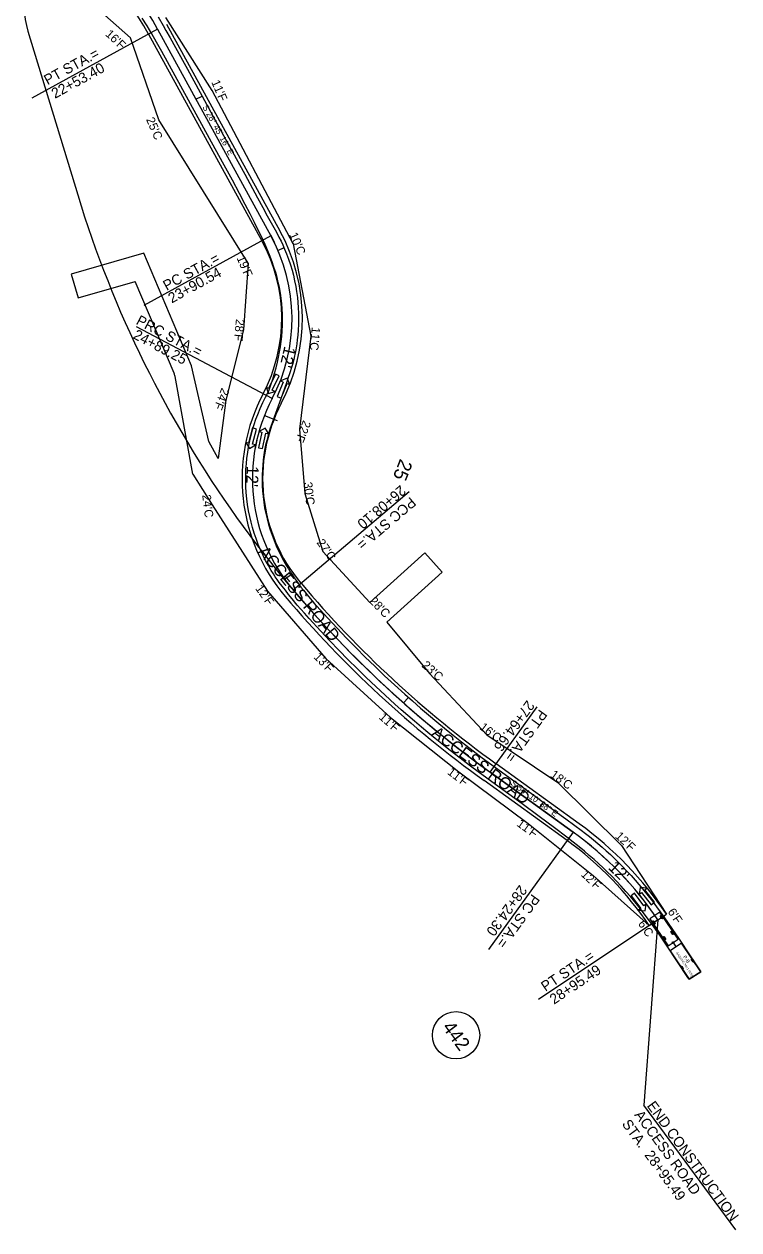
# Model space of a CAD drawing. Extents: x 1968740 to 1970715, y 796044 to 797557.
# Drawn here: x 1970299 to 1970715, y 796044 to 796745 of the extents above; entities that cross this region are included whole.
import ezdxf

# ---------------------------------------------------------------- set-up
doc = ezdxf.new("R2010")
doc.units = 0
for name, color, linetype in [('RD_EX_DV_TX_Prop', 7, 'Continuous'), ('RD_HC_CL_Rel', 7, 'Continuous'), ('RD_HC_Data_Rel', 7, 'Continuous'), ('RD_PD_ALT3_CL', 7, 'Continuous'), ('RD_PD_ALT4_CL', 7, 'Continuous'), ('RD_PD_ALT5_CL', 7, 'Continuous'), ('RD_PD_CstnLmt', 7, 'Continuous'), ('RD_PD_CstnLmt_TX', 7, 'Continuous'), ('RD_PD_Final_TrvlWay', 7, 'Continuous'), ('RD_PD_Final_TX', 7, 'Continuous'), ('RD_SHT_TX', 7, 'Continuous')]:
    doc.layers.add(name, color=color, linetype=linetype)

msp = doc.modelspace()

# ---------------------------------------------------------------- linework, layer by layer
at = {"layer": 'RD_EX_DV_TX_Prop'}
msp.add_circle((1970550.17, 796157.12), 13.75, dxfattribs=at)
at = {"layer": 'RD_HC_CL_Rel'}
for p, q in [((1970376.43, 796742.41), (1970442.41, 796622.18)), ((1970570.04, 796310.08), (1970618.4, 796275.17))]:
    msp.add_line(p, q, dxfattribs=at)
for centre, radius, start, end in [((1970201.1, 796646.2), 200, 28.75441, 54.46356), ((1970354.74, 796574.07), 100, 332.19932, 28.75441), ((1970531.65, 796480.79), 100, 152.19932, 220.29502), ((1970948.23, 796834.02), 646.17, 220.29502, 234.17718), ((1970501.34, 796113.01), 200, 33.78213, 54.17718)]:
    msp.add_arc(centre, radius, start, end, dxfattribs=at)
at = {"layer": 'RD_HC_Data_Rel'}
for p, q in [((1970376.43, 796742.41), (1970303.26, 796702.26)), ((1970396.45, 796705.94), (1970398.85, 796701.56)), ((1970398.85, 796701.56), (1970402.36, 796703.48)), ((1970442.41, 796622.18), (1970368.5, 796581.63)), ((1970442.15, 796622.66), (1970444.46, 796618.23)), ((1970446.56, 796613.69), (1970450.23, 796615.27)), ((1970443.2, 796527.43), (1970364.16, 796569.11)), ((1970438.7, 796517.67), (1970446.14, 796514.72)), ((1970434.23, 796503.37), (1970433.23, 796498.47)), ((1970431.69, 796483.57), (1970431.68, 796478.57)), ((1970455.38, 796416.12), (1970522.96, 796473.43)), ((1970450.4, 796422.51), (1970453.65, 796424.84)), ((1970519.59, 796350.48), (1970522.24, 796353.48)), ((1970570.04, 796310.08), (1970597.47, 796348.08)), ((1970598.69, 796289.4), (1970601.04, 796292.64)), ((1970618.4, 796275.17), (1970569.12, 796206.9)), ((1970667.57, 796224.22), (1970598.22, 796177.82))]:
    msp.add_line(p, q, dxfattribs=at)
at = {"layer": 'RD_PD_ALT3_CL'}
for p, q in [((1970376.43, 796742.41), (1970442.41, 796622.18)), ((1970618.4, 796275.17), (1970570.04, 796310.08))]:
    msp.add_line(p, q, dxfattribs=at)
for centre, radius, start, end in [((1970201.1, 796646.2), 200, 28.75441, 54.46356), ((1970354.74, 796574.07), 100, 332.19932, 28.75441), ((1970531.65, 796480.79), 100, 152.19932, 220.29502), ((1970948.23, 796834.02), 646.17, 220.29502, 234.17718), ((1970501.34, 796113.01), 200, 33.8013, 54.17718)]:
    msp.add_arc(centre, radius, start, end, dxfattribs=at)
at = {"layer": 'RD_PD_ALT4_CL'}
msp.add_line((1970301.07, 796741.13), (1970330.05, 796645.9), dxfattribs=at)
for centre, radius, start, end in [((1970350.34, 796756.12), 51.5, 165.49821, 196.92504), ((1970948.23, 796834.02), 646.17, 196.92504, 234.17718)]:
    msp.add_arc(centre, radius, start, end, dxfattribs=at)
at = {"layer": 'RD_PD_ALT5_CL'}
for p, q in [((1970376.43, 796742.41), (1970442.41, 796622.18)), ((1970618.4, 796275.17), (1970570.04, 796310.08)), ((1970668.78, 796228.71), (1970662.96, 796224.82)), ((1970662.96, 796224.82), (1970673.53, 796209.03)), ((1970662.96, 796224.82), (1970662.96, 796224.82)), ((1970679.35, 796212.92), (1970668.78, 796228.71)), ((1970669.13, 796226.59), (1970670.28, 796224.86)), ((1970669.23, 796226.66), (1970670.39, 796224.93)), ((1970669.34, 796226.73), (1970670.5, 796225)), ((1970664.57, 796223.54), (1970665.73, 796221.81)), ((1970664.68, 796223.61), (1970665.84, 796221.88)), ((1970664.79, 796223.69), (1970665.95, 796221.95)), ((1970675.24, 796217.45), (1970676.4, 796215.72)), ((1970675.35, 796217.52), (1970676.51, 796215.79)), ((1970675.46, 796217.59), (1970676.62, 796215.86)), ((1970670.69, 796214.4), (1970671.85, 796212.67)), ((1970670.8, 796214.47), (1970671.96, 796212.74)), ((1970670.91, 796214.54), (1970672.07, 796212.81)), ((1970673.53, 796209.03), (1970679.35, 796212.92)), ((1970681.43, 796210.71), (1970674.78, 796206.26)), ((1970676.44, 796210.98), (1970678.11, 796208.48)), ((1970692.56, 796194.09), (1970681.43, 796210.71)), ((1970674.78, 796206.26), (1970685.91, 796189.64)), ((1970674.78, 796206.26), (1970674.78, 796206.26)), ((1970680.99, 796197.22), (1970682.15, 796195.49)), ((1970681.09, 796197.3), (1970682.25, 796195.57)), ((1970681.2, 796197.37), (1970682.36, 796195.64)), ((1970687.2, 796201.39), (1970688.36, 796199.65)), ((1970687.31, 796201.46), (1970688.47, 796199.73)), ((1970687.42, 796201.53), (1970688.58, 796199.8)), ((1970685.91, 796189.64), (1970692.56, 796194.09))]:
    msp.add_line(p, q, dxfattribs=at)
for points in [[(1970685.14, 796190.78), (1970673.01, 796208.91), (1970668.67, 796215.29), (1970666.18, 796218.87), (1970663.84, 796222.14), (1970661.45, 796225.39), (1970659.23, 796228.34), (1970656.76, 796231.52), (1970654.24, 796234.66), (1970651.66, 796237.75), (1970649.02, 796240.8), (1970646.33, 796243.8), (1970643.59, 796246.75), (1970640.79, 796249.65), (1970638.17, 796252.25), (1970635.74, 796254.58), (1970633.03, 796257.09), (1970630.52, 796259.33), (1970627.71, 796261.76), (1970624.88, 796264.14), (1970621.75, 796266.69), (1970618.33, 796269.42), (1970614.62, 796272.31), (1970607.42, 796277.78), (1970598.56, 796284.37), (1970588.56, 796291.69), (1970573.08, 796302.93), (1970563.08, 796310.28), (1970558.52, 796313.69), (1970554.26, 796316.93), (1970550.02, 796320.2), (1970546.07, 796323.3), (1970541.89, 796326.63), (1970537.98, 796329.79), (1970533.85, 796333.19), (1970529.99, 796336.4), (1970525.91, 796339.86), (1970522.11, 796343.14), (1970518.33, 796346.44), (1970514.58, 796349.78), (1970508.88, 796354.94), (1970503.49, 796359.95), (1970497.91, 796365.25), (1970492.63, 796370.37), (1970487.41, 796375.56), (1970482.02, 796381.05), (1970476.69, 796386.59), (1970471.44, 796392.2), (1970464.67, 796399.59), (1970461.98, 796402.58), (1970457.78, 796407.37), (1970454.77, 796410.96), (1970452.69, 796413.57), (1970450.87, 796415.94), (1970448.94, 796418.33), (1970447.3, 796420.49), (1970446.12, 796422.13), (1970444.98, 796423.79), (1970443.88, 796425.47), (1970442.64, 796427.45), (1970440.96, 796430.33), (1970439.37, 796433.25), (1970437.89, 796436.23), (1970436.37, 796439.57), (1970435.09, 796442.64), (1970433.8, 796446.08), (1970432.73, 796449.24), (1970431.76, 796452.44), (1970430.9, 796455.67), (1970430.14, 796458.92), (1970429.49, 796462.2), (1970428.89, 796465.83), (1970428.46, 796469.15), (1970428.12, 796472.81), (1970427.91, 796476.12), (1970427.81, 796479.74), (1970427.83, 796483.02), (1970427.95, 796486.31), (1970428.18, 796489.58), (1970428.51, 796492.85), (1970428.94, 796496.1), (1970429.47, 796499.33), (1970430.18, 796502.85), (1970430.92, 796506.04), (1970431.77, 796509.19), (1970432.71, 796512.33), (1970433.76, 796515.45), (1970434.8, 796518.25), (1970436.19, 796521.67), (1970437.01, 796523.53), (1970437.73, 796525.09), (1970439.27, 796528.22), (1970441.3, 796532.02), (1970442.45, 796535.41), (1970443.55, 796538.82), (1970444.57, 796542.26), (1970445.44, 796545.41), (1970446.22, 796548.59), (1970446.86, 796551.48), (1970447.49, 796554.71), (1970447.98, 796557.64), (1970448.39, 796560.58), (1970448.71, 796563.53), (1970448.98, 796566.82), (1970449.14, 796570.12), (1970449.19, 796573.42), (1970449.14, 796576.39), (1970448.98, 796579.69), (1970448.74, 796582.65), (1970448.37, 796585.93), (1970447.95, 796588.86), (1970447.36, 796592.1), (1970446.74, 796595), (1970446.03, 796597.88), (1970445.23, 796600.73), (1970444.24, 796603.87), (1970443.15, 796606.98), (1970441.99, 796610.06), (1970440.62, 796613.42), (1970439.05, 796617.05), (1970437.28, 796620.95), (1970435.29, 796625.13), (1970432.95, 796629.86), (1970430.41, 796634.86), (1970427.51, 796640.43), (1970424.1, 796646.85), (1970420.03, 796654.43), (1970414.35, 796664.9), (1970406.73, 796678.84), (1970379.04, 796729.33), (1970375.95, 796734.81), (1970373.12, 796739.67), (1970370.39, 796744.21), (1970367.57, 796748.68)], [(1970376.77, 796749.48), (1970379.69, 796744.58), (1970381.37, 796741.67), (1970383.84, 796737.28), (1970386.94, 796731.71), (1970393.83, 796719.02), (1970416.11, 796678.4), (1970427.21, 796658.08), (1970434.71, 796644.2), (1970437.7, 796638.57), (1970440.19, 796633.82), (1970444.9, 796625.6), (1970446.05, 796623.53), (1970447.15, 796621.44), (1970448.35, 796619.02), (1970449.35, 796616.89), (1970450.42, 796614.43), (1970451.55, 796611.63), (1970452.72, 796608.49), (1970453.77, 796605.31), (1970454.73, 796602.1), (1970455.5, 796599.19), (1970456.26, 796595.93), (1970456.91, 796592.65), (1970457.4, 796589.68), (1970457.85, 796586.36), (1970458.16, 796583.36)], [(1970458.16, 796583.36), (1970458.39, 796580.36), (1970458.53, 796577.01), (1970458.57, 796573.67), (1970458.51, 796570.66), (1970458.35, 796567.32), (1970458.1, 796564.32), (1970457.81, 796561.66), (1970457.5, 796559.33), (1970457.13, 796557.02), (1970456.71, 796554.72), (1970456.24, 796552.43), (1970455.71, 796550.15), (1970455.13, 796547.88), (1970454.49, 796545.62), (1970453.47, 796542.41), (1970452.34, 796539.21), (1970451.52, 796536.69), (1970449.28, 796530.13), (1970447.47, 796525.14), (1970444.25, 796516.62), (1970442.91, 796512.78), (1970442.05, 796510.21), (1970441.25, 796507.62), (1970440.6, 796505.34), (1970440, 796503.05), (1970439.39, 796500.42), (1970438.8, 796497.45), (1970438.36, 796494.8), (1970437.96, 796491.81), (1970437.66, 796488.81), (1970437.47, 796486.13), (1970437.34, 796483.12), (1970437.31, 796480.1), (1970437.39, 796476.75), (1970437.57, 796473.76), (1970437.86, 796470.47), (1970438.28, 796467.19), (1970438.8, 796463.93), (1970439.44, 796460.69), (1970440.19, 796457.47), (1970441.05, 796454.28), (1970442.01, 796451.12), (1970443.09, 796447.99), (1970444.26, 796444.9), (1970445.54, 796441.85), (1970446.91, 796438.84), (1970448.38, 796435.88), (1970449.94, 796432.97), (1970451.58, 796430.11), (1970452.61, 796428.42), (1970453.67, 796426.75), (1970454.75, 796425.09), (1970456.05, 796423.18), (1970457.19, 796421.56), (1970458.55, 796419.69), (1970459.94, 796417.84), (1970461.36, 796416.01), (1970464.28, 796412.41), (1970467.51, 796408.62), (1970471.04, 796404.65), (1970475.51, 796399.74), (1970480.93, 796393.92), (1970486.41, 796388.17), (1970491.97, 796382.48), (1970497.37, 796377.09), (1970502.83, 796371.77), (1970508.6, 796366.28), (1970514.43, 796360.86), (1970520.33, 796355.52), (1970524.8, 796351.56), (1970529.56, 796347.42), (1970534.1, 796343.55), (1970538.93, 796339.5), (1970543.54, 796335.72), (1970548.44, 796331.76), (1970553.38, 796327.85), (1970558.34, 796323.99), (1970565.45, 796318.58), (1970573.14, 796312.84), (1970580.87, 796307.17), (1970596.15, 796296.11), (1970607.88, 796287.54), (1970613.99, 796283.03), (1970619.27, 796279.08), (1970623.06, 796276.32), (1970625.45, 796274.51), (1970627.8, 796272.68), (1970630.12, 796270.81), (1970632.66, 796268.71), (1970635.16, 796266.56), (1970637.62, 796264.38), (1970640.04, 796262.16), (1970642.43, 796259.9), (1970644.79, 796257.6), (1970647.1, 796255.27), (1970649.6, 796252.65), (1970652.06, 796249.99), (1970654.47, 796247.29), (1970656.62, 796244.79), (1970658.72, 796242.25), (1970662.04, 796238.15), (1970664.48, 796235.02), (1970666.87, 796231.86), (1970669.02, 796228.92), (1970671.13, 796225.96), (1970676.19, 796218.61), (1970679.52, 796213.67), (1970686.84, 796202.63), (1970692.56, 796194.09), (1970685.91, 796189.64), (1970685.14, 796190.78)]]:
    msp.add_lwpolyline(points, dxfattribs=at)
for points in [[(1970669.1, 796226.57), (1970669.37, 796226.75), (1970669.61, 796226.56), (1970670.45, 796225.32), (1970670.53, 796225.02), (1970670.26, 796224.84), (1970670.01, 796225.03), (1970669.18, 796226.27)], [(1970664.55, 796223.52), (1970664.82, 796223.7), (1970665.06, 796223.52), (1970665.89, 796222.27), (1970665.97, 796221.97), (1970665.7, 796221.79), (1970665.46, 796221.98), (1970664.63, 796223.23)], [(1970675.22, 796217.43), (1970675.49, 796217.61), (1970675.73, 796217.42), (1970676.57, 796216.18), (1970676.65, 796215.88), (1970676.38, 796215.7), (1970676.13, 796215.89), (1970675.3, 796217.13)], [(1970670.66, 796214.38), (1970670.93, 796214.56), (1970671.18, 796214.38), (1970672.01, 796213.13), (1970672.09, 796212.83), (1970671.82, 796212.65), (1970671.58, 796212.84), (1970670.75, 796214.09)], [(1970680.96, 796197.21), (1970681.23, 796197.39), (1970681.47, 796197.2), (1970682.31, 796195.95), (1970682.39, 796195.66), (1970682.12, 796195.48), (1970681.88, 796195.66), (1970681.04, 796196.91)], [(1970687.17, 796201.37), (1970687.44, 796201.55), (1970687.69, 796201.36), (1970688.52, 796200.11), (1970688.6, 796199.82), (1970688.33, 796199.64), (1970688.09, 796199.82), (1970687.26, 796201.07)]]:
    msp.add_lwpolyline(points, close=True, dxfattribs=at)
for centre, radius in [((1970376.43, 796742.41), 0.0417), ((1970376.43, 796742.41), 0.0417), ((1970442.41, 796622.18), 0.0417), ((1970442.41, 796622.18), 0.0417), ((1970443.2, 796527.43), 0.0417), ((1970443.2, 796527.43), 0.0417), ((1970455.38, 796416.12), 0.0417), ((1970455.38, 796416.12), 0.0417), ((1970570.04, 796310.08), 0.0417), ((1970570.04, 796310.08), 0.0417), ((1970618.4, 796275.17), 0.0417), ((1970618.4, 796275.17), 0.0417), ((1970667.54, 796224.27), 0.0417), ((1970676.44, 796210.98), 0.533)]:
    msp.add_circle(centre, radius, dxfattribs=at)
for centre, radius, start, end in [((1970201.1, 796646.2), 200, 28.75441, 54.46356), ((1970354.74, 796574.07), 100, 332.19932, 28.75441), ((1970531.65, 796480.79), 100, 152.19932, 220.29502), ((1970948.23, 796834.02), 646.17, 220.29502, 234.17718), ((1970501.34, 796113.01), 200, 33.8013, 54.17718)]:
    msp.add_arc(centre, radius, start, end, dxfattribs=at)
at = {"layer": 'RD_PD_CstnLmt'}
for p, q in [((1970360.82, 796737.41), (1970326.56, 796767.58)), ((1970408.3, 796706.75), (1970381.25, 796749.08)), ((1970377.22, 796689.69), (1970360.82, 796737.41)), ((1970455.31, 796617.46), (1970408.3, 796706.75)), ((1970429.18, 796606.19), (1970377.22, 796689.69)), ((1970455.31, 796617.46), (1970465.75, 796563.75)), ((1970368.42, 796612.15), (1970326.25, 796599.88)), ((1970396.24, 796546.51), (1970368.42, 796612.15)), ((1970429.18, 796606.19), (1970426.55, 796567.4)), ((1970326.25, 796599.88), (1970330.28, 796586.02)), ((1970330.28, 796586.02), (1970363.45, 796595.67)), ((1970386.11, 796542.22), (1970363.45, 796595.67)), ((1970426.55, 796567.4), (1970416.26, 796526.58)), ((1970465.75, 796563.75), (1970459.09, 796509.59)), ((1970396.94, 796483.46), (1970386.68, 796540.31)), ((1970406.38, 796502.58), (1970396.24, 796546.51)), ((1970416.26, 796526.58), (1970411.77, 796492.64)), ((1970459.09, 796509.59), (1970462.23, 796472.26)), ((1970411.77, 796492.64), (1970406.38, 796502.58)), ((1970396.94, 796483.46), (1970408.2, 796465.62)), ((1970462.23, 796472.26), (1970472.58, 796438.42)), ((1970408.2, 796465.62), (1970440.41, 796415.34)), ((1970472.58, 796438.42), (1970500.01, 796408.76)), ((1970532.05, 796437.68), (1970500.01, 796408.76)), ((1970542.1, 796426.54), (1970532.05, 796437.68)), ((1970509.81, 796397.4), (1970542.1, 796426.54)), ((1970440.41, 796415.34), (1970474.47, 796376.34)), ((1970509.81, 796397.4), (1970534.65, 796367.47)), ((1970474.47, 796376.34), (1970512.04, 796341.96)), ((1970534.65, 796367.47), (1970568.16, 796331.89)), ((1970512.04, 796341.96), (1970551.8, 796310.28)), ((1970568.16, 796331.89), (1970609.4, 796304.23)), ((1970551.8, 796310.28), (1970592.12, 796280.3)), ((1970609.4, 796304.23), (1970646.37, 796267.53)), ((1970592.12, 796280.3), (1970629.97, 796250.06)), ((1970646.37, 796267.53), (1970672.56, 796227.55)), ((1970629.97, 796250.06), (1970662.59, 796220.88))]:
    msp.add_line(p, q, dxfattribs=at)
msp.add_arc((1970377.82, 796538.71), 9, 10.23288, 22.97111, dxfattribs=at)
at = {"layer": 'RD_PD_Final_TrvlWay'}
for p, q in [((1970381.69, 796745.3), (1970447.67, 796625.07)), ((1970371.17, 796739.53), (1970437.15, 796619.29)), ((1970621.91, 796280.04), (1970573.55, 796314.95)), ((1970614.89, 796270.31), (1970566.53, 796305.22)), ((1970662.59, 796220.88), (1970672.56, 796227.55))]:
    msp.add_line(p, q, dxfattribs=at)
for centre, radius, start, end in [((1970201.1, 796646.2), 194, 28.75441, 54.46356), ((1970354.74, 796574.07), 106, 332.19932, 28.75441), ((1970354.74, 796574.07), 94, 332.19932, 28.75441), ((1970531.65, 796480.79), 106, 152.19932, 220.29502), ((1970531.65, 796480.79), 94, 152.19932, 220.29502), ((1970948.23, 796834.02), 640.17, 220.29502, 234.17718), ((1970948.23, 796834.02), 652.17, 220.29502, 234.17718), ((1970501.34, 796113.01), 206, 33.78213, 54.17718), ((1970501.34, 796113.01), 194, 33.78213, 54.17718)]:
    msp.add_arc(centre, radius, start, end, dxfattribs=at)
at = {"layer": 'RD_PD_Final_TX'}
for p in [(1970667.57, 796224.22), (1970712.99, 796043.88)]:
    msp.add_line(p, (1970659.47, 796116.49), dxfattribs=at)
at = {"layer": 'RD_SHT_TX'}
for points in [[(1970447.23, 796540.62), (1970445.06, 796541.66), (1970441.09, 796533.4), (1970439.62, 796534.1), (1970440.95, 796530.33), (1970444.72, 796531.65), (1970443.25, 796532.36)], [(1970446.17, 796528.63), (1970448.39, 796527.72), (1970451.89, 796536.19), (1970453.4, 796535.57), (1970451.86, 796539.26), (1970448.17, 796537.73), (1970449.67, 796537.11)], [(1970434.11, 796509.77), (1970431.78, 796510.37), (1970429.5, 796501.49), (1970427.93, 796501.89), (1970429.96, 796498.45), (1970433.41, 796500.48), (1970431.83, 796500.89)], [(1970435.19, 796498.91), (1970437.53, 796498.38), (1970439.58, 796507.32), (1970441.16, 796506.95), (1970439.04, 796510.34), (1970435.65, 796508.22), (1970437.24, 796507.85)], [(1970654.01, 796239.7), (1970652.09, 796238.26), (1970657.61, 796230.93), (1970656.31, 796229.95), (1970660.27, 796229.39), (1970660.83, 796233.35), (1970659.53, 796232.37)], [(1970663.72, 796232.95), (1970665.61, 796234.44), (1970659.93, 796241.65), (1970661.21, 796242.65), (1970657.24, 796243.13), (1970656.77, 796239.15), (1970658.05, 796240.16)]]:
    msp.add_lwpolyline(points, close=True, dxfattribs=at)

# ---------------------------------------------------------------- texts
at = {"layer": 'RD_EX_DV_TX_Prop'}
msp.add_text('442', height=8, rotation=306.50592, dxfattribs=at).set_placement((1970541.83, 796161.67))
at = {"layer": 'RD_HC_Data_Rel'}
for s, height, rotation, p in [('PT STA.=', 6, 28.75441, (1970312.47, 796709.67)), ('22+53.40', 6, 28.75441, (1970316.8, 796701.78)), ('S 28%%d 45\' 16" E', 3.6, 298.75441, (1970402.46, 796697.06)), ('PC STA.=', 6, 28.75441, (1970381.77, 796590.05)), ('23+90.54', 6, 28.75441, (1970384.73, 796582.76)), ('PRC STA.=', 6, 332.19932, (1970363.51, 796571.01)), ('24+89.25', 6, 332.19932, (1970361.78, 796562.73)), ('25', 8, 248.35841, (1970517.7, 796492.83)), ('26+08.10', 6, 220.29502, (1970517.83, 796477.42)), ('PCC STA.=', 6, 220.29502, (1970523.65, 796470.55)), ('27+64.66', 6, 234.17718, (1970591.49, 796352.39)), ('PT STA.=', 6, 234.17718, (1970598.79, 796347.12)), ('S 54%%d 10\' 38" E', 3.6, 324.17718, (1970581.6, 796302.97)), ('28+24.30', 6, 234.17718, (1970587.16, 796244.93)), ('PC STA.=', 6, 234.17718, (1970594.46, 796239.66)), ('PT STA.=', 6, 33.78213, (1970602.19, 796182.3)), ('28+95.49', 6, 33.78213, (1970607.19, 796174.82))]:
    msp.add_text(s, height=height, rotation=rotation, dxfattribs=at).set_placement(p)
at = {"layer": 'RD_PD_ALT5_CL'}
for s, height, p in [('AASHTO 2011 (US)', 1.3333, (1970678.04, 796204.97)), ('P-B', 2, (1970682.19, 796202.68)), ('(c) 2021 Transoft Solutions, Inc. All rights reserved.', 0.08, (1970682.73, 796201.51))]:
    msp.add_text(s, height=height, rotation=303.8013, dxfattribs=at).set_placement(p)
at = {"layer": 'RD_PD_CstnLmt_TX'}
for s, rotation, p in [("16'F", 316.63814, (1970345.78, 796739.02)), ("11'F", 293.33604, (1970407.68, 796711.59)), ("25'C", 293.33604, (1970369.72, 796689.86)), ("10'C", 293.33604, (1970452.97, 796622.9)), ("19'F", 293.33604, (1970422.39, 796609.3)), ("28'F", 264.68812, (1970422.13, 796573.87)), ("11'C", 264.68812, (1970466.26, 796569.17)), ("24'F", 248.35842, (1970413.84, 796534.03)), ("22'F", 248.35842, (1970461.31, 796515.19)), ("30'C", 277.00627, (1970461.45, 796478.62)), ("24'C", 277.00627, (1970402.46, 796471.37)), ("27'C", 305.6542, (1970468.84, 796443.62)), ("12'F", 305.6542, (1970433.12, 796416.94)), ("28'C", 314.01029, (1970499.34, 796409.28)), ("13'F", 314.01029, (1970467.02, 796376.86)), ("23'C", 318.44376, (1970529.85, 796371.72)), ("11'F", 318.44376, (1970504.93, 796341.58)), ("16'C", 322.87723, (1970563.44, 796335.47)), ("11'F", 322.87723, (1970544.74, 796309.35)), ("18'C", 324.17718, (1970604.6, 796307.7)), ("11'F", 324.17718, (1970585.09, 796279.21)), ("12'F", 316.8148, (1970642.41, 796272.43)), ("12'F", 316.8148, (1970622.5, 796250.21)), ("6'F", 303.78286, (1970673.08, 796228.92)), ("6'C", 303.78286, (1970655.84, 796221.98))]:
    msp.add_text(s, height=5, rotation=rotation, dxfattribs=at).set_placement(p)
at = {"layer": 'RD_PD_Final_TX'}
for s, p in [('END CONSTRUCTION', (1970660.96, 796116.04)), ('ACCESS ROAD', (1970653.69, 796110.74)), ('STA.  28+95.49', (1970646.41, 796105.44))]:
    msp.add_text(s, height=5.9996, rotation=306.06576, dxfattribs=at).set_placement(p)
at = {"layer": 'RD_SHT_TX'}
for s, rotation, p in [("12'", 256.72931, (1970450.37, 796558.32)), ("12'", 267.80931, (1970428.42, 796488.41)), ('ACCESS ROAD', 309.24188, (1970434.72, 796438.16)), ('ACCESS ROAD', 323.2251, (1970535.31, 796331.74)), ("12'", 315.68937, (1970638.26, 796254.23))]:
    msp.add_text(s, height=7, rotation=rotation, dxfattribs=at).set_placement(p)

doc.saveas('drawing.dxf')
